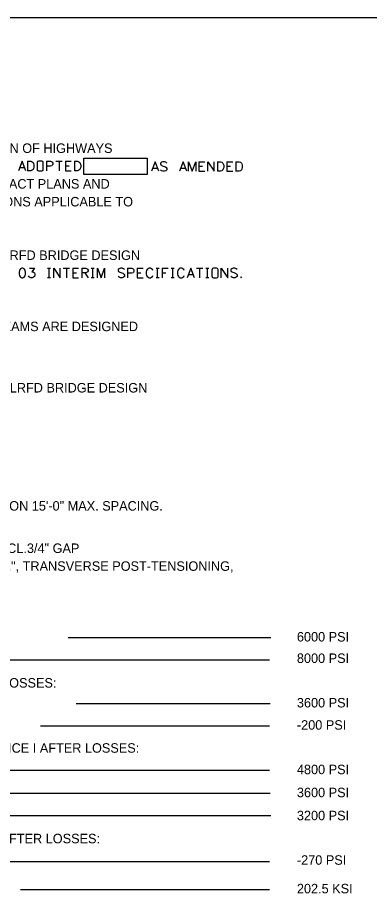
# Model space of a CAD drawing. Extents: x 762.3 to 790.4, y -1231.3 to -1213.2.
# Drawn here: x 767.98 to 771.46, y -1222.26 to -1213.6 of the extents above; entities that cross this region are included whole.
import ezdxf

# ---------------------------------------------------------------- set-up
doc = ezdxf.new("R2010")
doc.units = 0
doc.layers.add('Default', color=7, linetype='Continuous')

msp = doc.modelspace()

# ---------------------------------------------------------------- linework, layer by layer
at = {"layer": 'Default'}
for p, q in [((763.5542, -1213.5986), (789.9542, -1213.5986)), ((768.4841, -1219.7275), (770.4865, -1219.7275)), ((767.9109, -1219.9474), (770.4708, -1219.9474)), ((768.5627, -1220.3793), (770.4787, -1220.3793)), ((768.2093, -1220.5991), (770.4708, -1220.5991)), ((766.4975, -1221.0389), (770.4708, -1221.0389)), ((766.3247, -1221.2666), (770.4787, -1221.2666)), ((766.9529, -1221.4865), (770.4865, -1221.4865)), ((766.466, -1221.9419), (770.4708, -1221.9419)), ((768.013, -1222.2167), (770.4708, -1222.2167))]:
    msp.add_line(p, q, dxfattribs=at)
for points in [[(768.0648, -1215.1134), (768.0287, -1215.0196), (767.9925, -1215.1134)], [(768.0818, -1215.0196), (768.0818, -1215.1134)], [(768.0818, -1215.0196), (768.1136, -1215.0196), (768.1269, -1215.0241), (768.1357, -1215.0329), (768.1401, -1215.0418), (768.1446, -1215.0551), (768.1446, -1215.078), (768.1401, -1215.0912), (768.1357, -1215.1001), (768.1269, -1215.109), (768.1136, -1215.1134), (768.0818, -1215.1134)], [(768.1756, -1215.0986), (768.1763, -1215.1023), (768.1778, -1215.106), (768.1807, -1215.1097), (768.1837, -1215.1119), (768.1903, -1215.1134), (768.2213, -1215.1134), (768.2287, -1215.1119), (768.2317, -1215.1097), (768.2346, -1215.106), (768.2361, -1215.1023), (768.2368, -1215.0986), (768.2368, -1215.0344), (768.2361, -1215.0307), (768.2346, -1215.027), (768.2317, -1215.0233), (768.2302, -1215.0219), (768.2213, -1215.0196), (768.1903, -1215.0196), (768.1822, -1215.0219), (768.1807, -1215.0233), (768.1778, -1215.027), (768.1763, -1215.0307), (768.1756, -1215.0344), (768.1756, -1215.0986)], [(768.2678, -1215.0196), (768.2678, -1215.1134)], [(768.2678, -1215.0196), (768.3084, -1215.0196), (768.3217, -1215.0241), (768.3262, -1215.0285), (768.3306, -1215.0374), (768.3306, -1215.0506), (768.3262, -1215.0595), (768.3217, -1215.0639), (768.3084, -1215.0684), (768.2678, -1215.0684)], [(768.3616, -1215.0196), (768.4243, -1215.0196)], [(768.3933, -1215.0196), (768.3933, -1215.1134)], [(768.4553, -1215.0196), (768.4553, -1215.1134)], [(768.4553, -1215.0196), (768.5137, -1215.0196)], [(768.5446, -1215.0196), (768.5446, -1215.1134)], [(768.5446, -1215.0196), (768.5764, -1215.0196), (768.5897, -1215.0241), (768.5985, -1215.0329), (768.603, -1215.0418), (768.6074, -1215.0551), (768.6074, -1215.078), (768.603, -1215.0912), (768.5985, -1215.1001), (768.5897, -1215.109), (768.5764, -1215.1134), (768.5446, -1215.1134)], [(769.3773, -1215.1178), (769.3411, -1215.0241), (769.3049, -1215.1178)], [(769.457, -1215.0374), (769.4481, -1215.0285), (769.4349, -1215.0241), (769.4171, -1215.0241), (769.4039, -1215.0285), (769.3943, -1215.0374), (769.3943, -1215.0462), (769.3987, -1215.0551), (769.4039, -1215.0595), (769.4127, -1215.0639), (769.4393, -1215.0728), (769.4481, -1215.078), (769.4526, -1215.0824), (769.457, -1215.0912), (769.457, -1215.1045), (769.4481, -1215.1134), (769.4349, -1215.1178), (769.4171, -1215.1178), (769.4039, -1215.1134), (769.3943, -1215.1045)], [(769.6541, -1215.1178), (769.6179, -1215.0241), (769.5818, -1215.1178)], [(769.6711, -1215.1178), (769.6711, -1215.0241), (769.7072, -1215.1178), (769.7427, -1215.0241), (769.7427, -1215.1178)], [(769.7737, -1215.0241), (769.7737, -1215.1178)], [(769.7737, -1215.0241), (769.832, -1215.0241)], [(769.863, -1215.1178), (769.863, -1215.0241), (769.9257, -1215.1178), (769.9257, -1215.0241)], [(769.9567, -1215.0241), (769.9567, -1215.1178)], [(769.9567, -1215.0241), (769.9885, -1215.0241), (770.0018, -1215.0285), (770.0106, -1215.0374), (770.015, -1215.0462), (770.0195, -1215.0595), (770.0195, -1215.0824), (770.015, -1215.0957), (770.0106, -1215.1045), (770.0018, -1215.1134), (769.9885, -1215.1178), (769.9567, -1215.1178)], [(770.0505, -1215.0241), (770.0505, -1215.1178)], [(770.0505, -1215.0241), (770.1088, -1215.0241)], [(770.1398, -1215.0241), (770.1398, -1215.1178)], [(770.1398, -1215.0241), (770.1715, -1215.0241), (770.1848, -1215.0285), (770.1937, -1215.0374), (770.1981, -1215.0462), (770.2025, -1215.0595), (770.2025, -1215.0824), (770.1981, -1215.0957), (770.1937, -1215.1045), (770.1848, -1215.1134), (770.1715, -1215.1178), (770.1398, -1215.1178)], [(768.0043, -1215.0824), (768.053, -1215.0824)], [(768.4553, -1215.0639), (768.4915, -1215.0639)], [(768.4553, -1215.1134), (768.5137, -1215.1134)], [(769.3168, -1215.0868), (769.3655, -1215.0868)], [(769.5936, -1215.0868), (769.6423, -1215.0868)], [(769.7737, -1215.0684), (769.8098, -1215.0684)], [(769.7737, -1215.1178), (769.832, -1215.1178)], [(770.0505, -1215.0684), (770.0867, -1215.0684)], [(770.0505, -1215.1178), (770.1088, -1215.1178)], [(768.025, -1216.0771), (768.0117, -1216.0816), (768.0028, -1216.0956), (767.9984, -1216.1177), (767.9984, -1216.131), (768.0028, -1216.1532), (768.0117, -1216.1665), (768.025, -1216.1709), (768.0338, -1216.1709), (768.0471, -1216.1665), (768.0567, -1216.1532), (768.0611, -1216.131), (768.0611, -1216.1177), (768.0567, -1216.0956), (768.0471, -1216.0816), (768.0338, -1216.0771), (768.025, -1216.0771)], [(768.101, -1216.0771), (768.1505, -1216.0771), (768.1231, -1216.1133), (768.1364, -1216.1133), (768.1453, -1216.1177), (768.1505, -1216.1222), (768.1549, -1216.1355), (768.1549, -1216.1443), (768.1505, -1216.1576), (768.1408, -1216.1665), (768.1276, -1216.1709), (768.1143, -1216.1709), (768.101, -1216.1665), (768.0966, -1216.162), (768.0921, -1216.1532)], [(768.2796, -1216.0771), (768.3092, -1216.0771)], [(768.2944, -1216.1709), (768.2944, -1216.0771)], [(768.3402, -1216.1709), (768.3402, -1216.0771), (768.4029, -1216.1709), (768.4029, -1216.0771)], [(768.4339, -1216.0771), (768.4967, -1216.0771)], [(768.4657, -1216.0771), (768.4657, -1216.1709)], [(768.5277, -1216.0771), (768.5277, -1216.1709)], [(768.5277, -1216.0771), (768.586, -1216.0771)], [(768.617, -1216.0771), (768.617, -1216.1709)], [(768.617, -1216.0771), (768.6576, -1216.0771), (768.6709, -1216.0816), (768.6753, -1216.086), (768.6797, -1216.0949), (768.6797, -1216.1037), (768.6753, -1216.1126), (768.6709, -1216.117), (768.6576, -1216.1214), (768.617, -1216.1214)], [(768.7107, -1216.0771), (768.7402, -1216.0771)], [(768.7255, -1216.1709), (768.7255, -1216.0771)], [(768.7712, -1216.1709), (768.7712, -1216.0771), (768.8074, -1216.1709), (768.8429, -1216.0771), (768.8429, -1216.1709)], [(769.0392, -1216.0904), (769.0304, -1216.0816), (769.0171, -1216.0771), (768.9994, -1216.0771), (768.9861, -1216.0816), (768.9765, -1216.0904), (768.9765, -1216.0993), (768.9809, -1216.1081), (768.9861, -1216.1126), (768.9949, -1216.117), (769.0215, -1216.1259), (769.0304, -1216.131), (769.0348, -1216.1355), (769.0392, -1216.1443), (769.0392, -1216.1576), (769.0304, -1216.1665), (769.0171, -1216.1709), (768.9994, -1216.1709), (768.9861, -1216.1665), (768.9765, -1216.1576)], [(769.0702, -1216.0771), (769.0702, -1216.1709)], [(769.0702, -1216.0771), (769.1108, -1216.0771), (769.1241, -1216.0816), (769.1285, -1216.086), (769.133, -1216.0949), (769.133, -1216.1081), (769.1285, -1216.117), (769.1241, -1216.1214), (769.1108, -1216.1259), (769.0702, -1216.1259)], [(769.164, -1216.0771), (769.164, -1216.1709)], [(769.164, -1216.0771), (769.2223, -1216.0771)], [(769.3204, -1216.0993), (769.316, -1216.0904), (769.3072, -1216.0816), (769.2983, -1216.0771), (769.2806, -1216.0771), (769.2717, -1216.0816), (769.2629, -1216.0904), (769.2577, -1216.0993), (769.2533, -1216.1126), (769.2533, -1216.1355), (769.2577, -1216.1487), (769.2629, -1216.1576), (769.2717, -1216.1665), (769.2806, -1216.1709), (769.2983, -1216.1709), (769.3072, -1216.1665), (769.316, -1216.1576), (769.3204, -1216.1487)], [(769.3515, -1216.0771), (769.381, -1216.0771)], [(769.3662, -1216.1709), (769.3662, -1216.0771)], [(769.412, -1216.0771), (769.412, -1216.1709)], [(769.412, -1216.0771), (769.4703, -1216.0771)], [(769.5013, -1216.0771), (769.5308, -1216.0771)], [(769.5161, -1216.1709), (769.5161, -1216.0771)], [(769.629, -1216.0993), (769.6246, -1216.0904), (769.6157, -1216.0816), (769.6068, -1216.0771), (769.5891, -1216.0771), (769.5803, -1216.0816), (769.5714, -1216.0904), (769.5662, -1216.0993), (769.5618, -1216.1126), (769.5618, -1216.1355), (769.5662, -1216.1487), (769.5714, -1216.1576), (769.5803, -1216.1665), (769.5891, -1216.1709), (769.6068, -1216.1709), (769.6157, -1216.1665), (769.6246, -1216.1576), (769.629, -1216.1487)], [(769.7323, -1216.1709), (769.6962, -1216.0771), (769.66, -1216.1709)], [(769.7493, -1216.0771), (769.8121, -1216.0771)], [(769.7811, -1216.0771), (769.7811, -1216.1709)], [(769.8431, -1216.0771), (769.8726, -1216.0771)], [(769.8578, -1216.1709), (769.8578, -1216.0771)], [(769.9036, -1216.1561), (769.9043, -1216.1598), (769.9058, -1216.1635), (769.9088, -1216.1672), (769.9117, -1216.1694), (769.9183, -1216.1709), (769.9493, -1216.1709), (769.9567, -1216.1694), (769.9597, -1216.1672), (769.9626, -1216.1635), (769.9641, -1216.1598), (769.9649, -1216.1561), (769.9649, -1216.0919), (769.9641, -1216.0882), (769.9626, -1216.0845), (769.9597, -1216.0808), (769.9582, -1216.0794), (769.9493, -1216.0771), (769.9183, -1216.0771), (769.9102, -1216.0794), (769.9088, -1216.0808), (769.9058, -1216.0845), (769.9043, -1216.0882), (769.9036, -1216.0919), (769.9036, -1216.1561)], [(769.9958, -1216.1709), (769.9958, -1216.0771), (770.0586, -1216.1709), (770.0586, -1216.0771)], [(770.1523, -1216.0904), (770.1435, -1216.0816), (770.1302, -1216.0771), (770.1125, -1216.0771), (770.0992, -1216.0816), (770.0896, -1216.0904), (770.0896, -1216.0993), (770.094, -1216.1081), (770.0992, -1216.1126), (770.1081, -1216.117), (770.1346, -1216.1259), (770.1435, -1216.131), (770.1479, -1216.1355), (770.1523, -1216.1443), (770.1523, -1216.1576), (770.1435, -1216.1665), (770.1302, -1216.1709), (770.1125, -1216.1709), (770.0992, -1216.1665), (770.0896, -1216.1576)], [(768.3092, -1216.1709), (768.2796, -1216.1709)], [(768.5277, -1216.1214), (768.5638, -1216.1214)], [(768.5277, -1216.1709), (768.586, -1216.1709)], [(768.6487, -1216.1214), (768.6797, -1216.1709)], [(768.7402, -1216.1709), (768.7107, -1216.1709)], [(769.164, -1216.1214), (769.2001, -1216.1214)], [(769.164, -1216.1709), (769.2223, -1216.1709)], [(769.381, -1216.1709), (769.3515, -1216.1709)], [(769.412, -1216.1214), (769.4482, -1216.1214)], [(769.5308, -1216.1709), (769.5013, -1216.1709)], [(769.6718, -1216.1399), (769.7205, -1216.1399)], [(769.8726, -1216.1709), (769.8431, -1216.1709)], [(770.1915, -1216.162), (770.187, -1216.1665), (770.1915, -1216.1709), (770.1959, -1216.1665), (770.1915, -1216.162)]]:
    msp.add_lwpolyline(points, dxfattribs=at)
msp.add_lwpolyline([(768.6373, -1214.988), (769.2647, -1214.988), (769.2647, -1215.1487), (768.6373, -1215.1487)], close=True, dxfattribs=at)

# ---------------------------------------------------------------- texts
for s, p in [('THE WEST VIRGINIA DEPARTMENT OF TRANSPORTATION, DIVISION OF HIGHWAYS', (763.8433, -1214.9371)), ('BY THE CURRENT SUPPLEMENTAL SPECIFICATIONS.  THE CONTRACT PLANS AND ', (763.8433, -1215.2896)), ('CONTRACT SPECIAL PROVISIONS ARE THE GOVERNING PROVISIONS APPLICABLE TO', (763.8433, -1215.4659)), ('ALL BEAMS ARE DESIGNED IN ACCORDANCE WITH THE AASHTO LRFD BRIDGE DESIGN ', (763.8433, -1215.9946)), ('ALL STANDARD ADJACENT PRESTRESSED CONCRETE BRIDGE BEAMS ARE DESIGNED', (763.8512, -1216.6987)), ('HL-93 LIVE LOAD IN ACCORDANCE WITH THE AASHTO LRFD BRIDGE DESIGN', (764.5697, -1217.3052)), ('DIAPHRAGM DEAD LOAD, NUMBER REQUIRED BASED ON 15\'-0" MAX. SPACING.', (764.5781, -1218.4726)), ('TWO LANE BRIDGE WITH AN OVERALL WIDTH OF 24\'-5" (INCL.3/4" GAP', (764.3223, -1218.8914)), ('BETWEEN ADJ. BEAMS),  A CURB-TO-CURB WIDTH OF 22\'-1", TRANSVERSE POST-TENSIONING, ', (764.3223, -1219.0677)), ('6000 PSI', (770.7424, -1219.7665)), ('8000 PSI', (770.7424, -1219.9785)), ('TEMPORARY STRESS LIMITS IN CONCRETE BEFORE LOSSES:', (764.5775, -1220.2219)), ('3600 PSI', (770.7424, -1220.4183)), ('-200 PSI', (770.7424, -1220.6381)), ('COMPRESSIVE STRESS LIMITS IN CONCRETE @ SERVICE I AFTER LOSSES:', (764.5579, -1220.8658)), ('4800 PSI', (770.7424, -1221.0779)), ('3600 PSI', (770.7424, -1221.3056)), ('3200 PSI', (770.7424, -1221.5333)), ('TENSILE STRESS LIMIT IN CONCRETE @ SERVICE III AFTER LOSSES:', (764.5814, -1221.761)), ('-270 PSI', (770.7424, -1221.9731)), ('202.5 KSI', (770.7424, -1222.2558))]:
    msp.add_text(s, height=0.09375, dxfattribs=at).set_placement(p)

doc.saveas('drawing.dxf')
